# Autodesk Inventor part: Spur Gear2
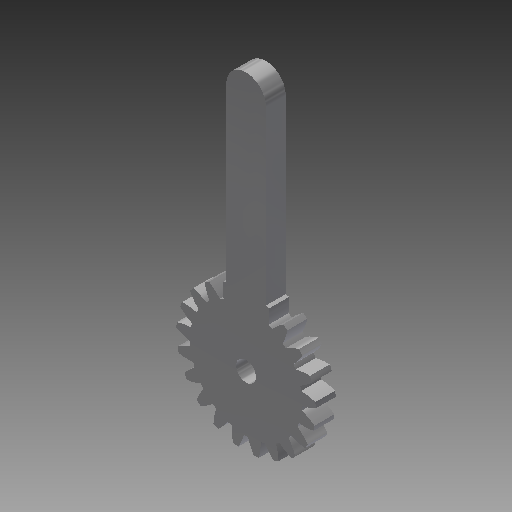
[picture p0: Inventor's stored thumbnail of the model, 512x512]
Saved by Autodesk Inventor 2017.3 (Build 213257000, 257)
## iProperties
Created: 2020-03
Part Number: Spur Gear2
Material: Steel
Document SubType Name: Modeling
Designer: Tim_G
Categories: <?xml version="1.0" encoding="UTF-16"?> <MemberInstance><Categories><FamilyTemplate><FamilyTemplateParameter ValueType="xs:double" Id="1" ObjectReferenceKey="da
Density: 1 g/cm^3
Appearance: Steel
CustomPartVersion: 1
Author: Tim_G
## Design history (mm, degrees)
sketch "Sketch1"
  geometry: C1 r 17.514 at (0, 0)
  constraints: 1 centre point
  dimensions: "d0" = 35.02752 diameter of C1 (= da_da)
extrude "Extrusion1" new body sketch "Sketch1" distance "d1" = 5 (= da_b); taper "d2" = 0 deg
workplane "Work Plane2"
sketch "Sketch2"
  geometry: C1 r 17.514 at (0, 0) reference; C2 r 15.991 at (0, 0)
  constraints: 1 centre point, 1 coincident
  dimensions: "d3" = 31.98165 diameter of C2 (= da_dw)
feature "Pitch Diameter" sketch "Sketch2" dims "d4" = 10, "d5" = 0
workplane "Work Plane8"
workplane "Work Plane9"
feature "Spur Gear" dims "da_b" = 5, "da_d" = 31.98165, "da_aw" = 25.12844, "da_da" = 35.02752, "da_df" = 28.17431, "da_dw" = 31.98165, angle "da_beta" = 0 deg, "da_lefttooth" = 0, "da_righttooth" = 0
sketch "Sketch4"
  geometry: L1 (0, 0)-(0, 60); L2 (5, 0)-(5, 60); L3 (-5, 60)-(-5, 0); A1 r 5 centre (0, 0) between (-5, 0) and (5, 0); A2 r 5 centre (0, 60) between (5, 60) and (-5, 60); 1 further point
  constraints: 8 end point, 4 point on circle, 4 tangent, 2 centre point, 1 midpoint, 1 parallel, 1 vertical
  dimensions: "d52" = 60 distance of L1.start L1.end; "d53" = 10 diameter of A2
extrude "Extrusion3" join sketch "Sketch4" distance "d54" = 5; taper "d55" = 0 deg
sketch "Sketch3"
  geometry: C1 r 2.5 at (0, 0); 1 further point
  constraints: 1 centre point, 1 coincident
  dimensions: "d49" = 5 diameter of C1
extrude "Extrusion2" cut sketch "Sketch3" distance "d50" = 5; taper "d51" = 0 deg
body "Solid1"
body "Srf1"
other parameters: "d16" = 25.12844 (= da_aw), "d17" = 0, "d34" = 1.496 (computed from da_z), "d39" = 0, "d41" = 0, "d43" = 25.12844 (= da_aw), "d46" = 25.12844 (= da_aw), "d47" = 0, "d48" = 0
